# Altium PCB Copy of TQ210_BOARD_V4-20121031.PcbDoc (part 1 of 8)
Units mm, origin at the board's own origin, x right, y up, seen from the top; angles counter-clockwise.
Board outline 191.2 x 131.27 mm, 2 copper layers (TopLayer, BottomLayer); 362 components, 455 nets, 1594 pads, 630 vias.
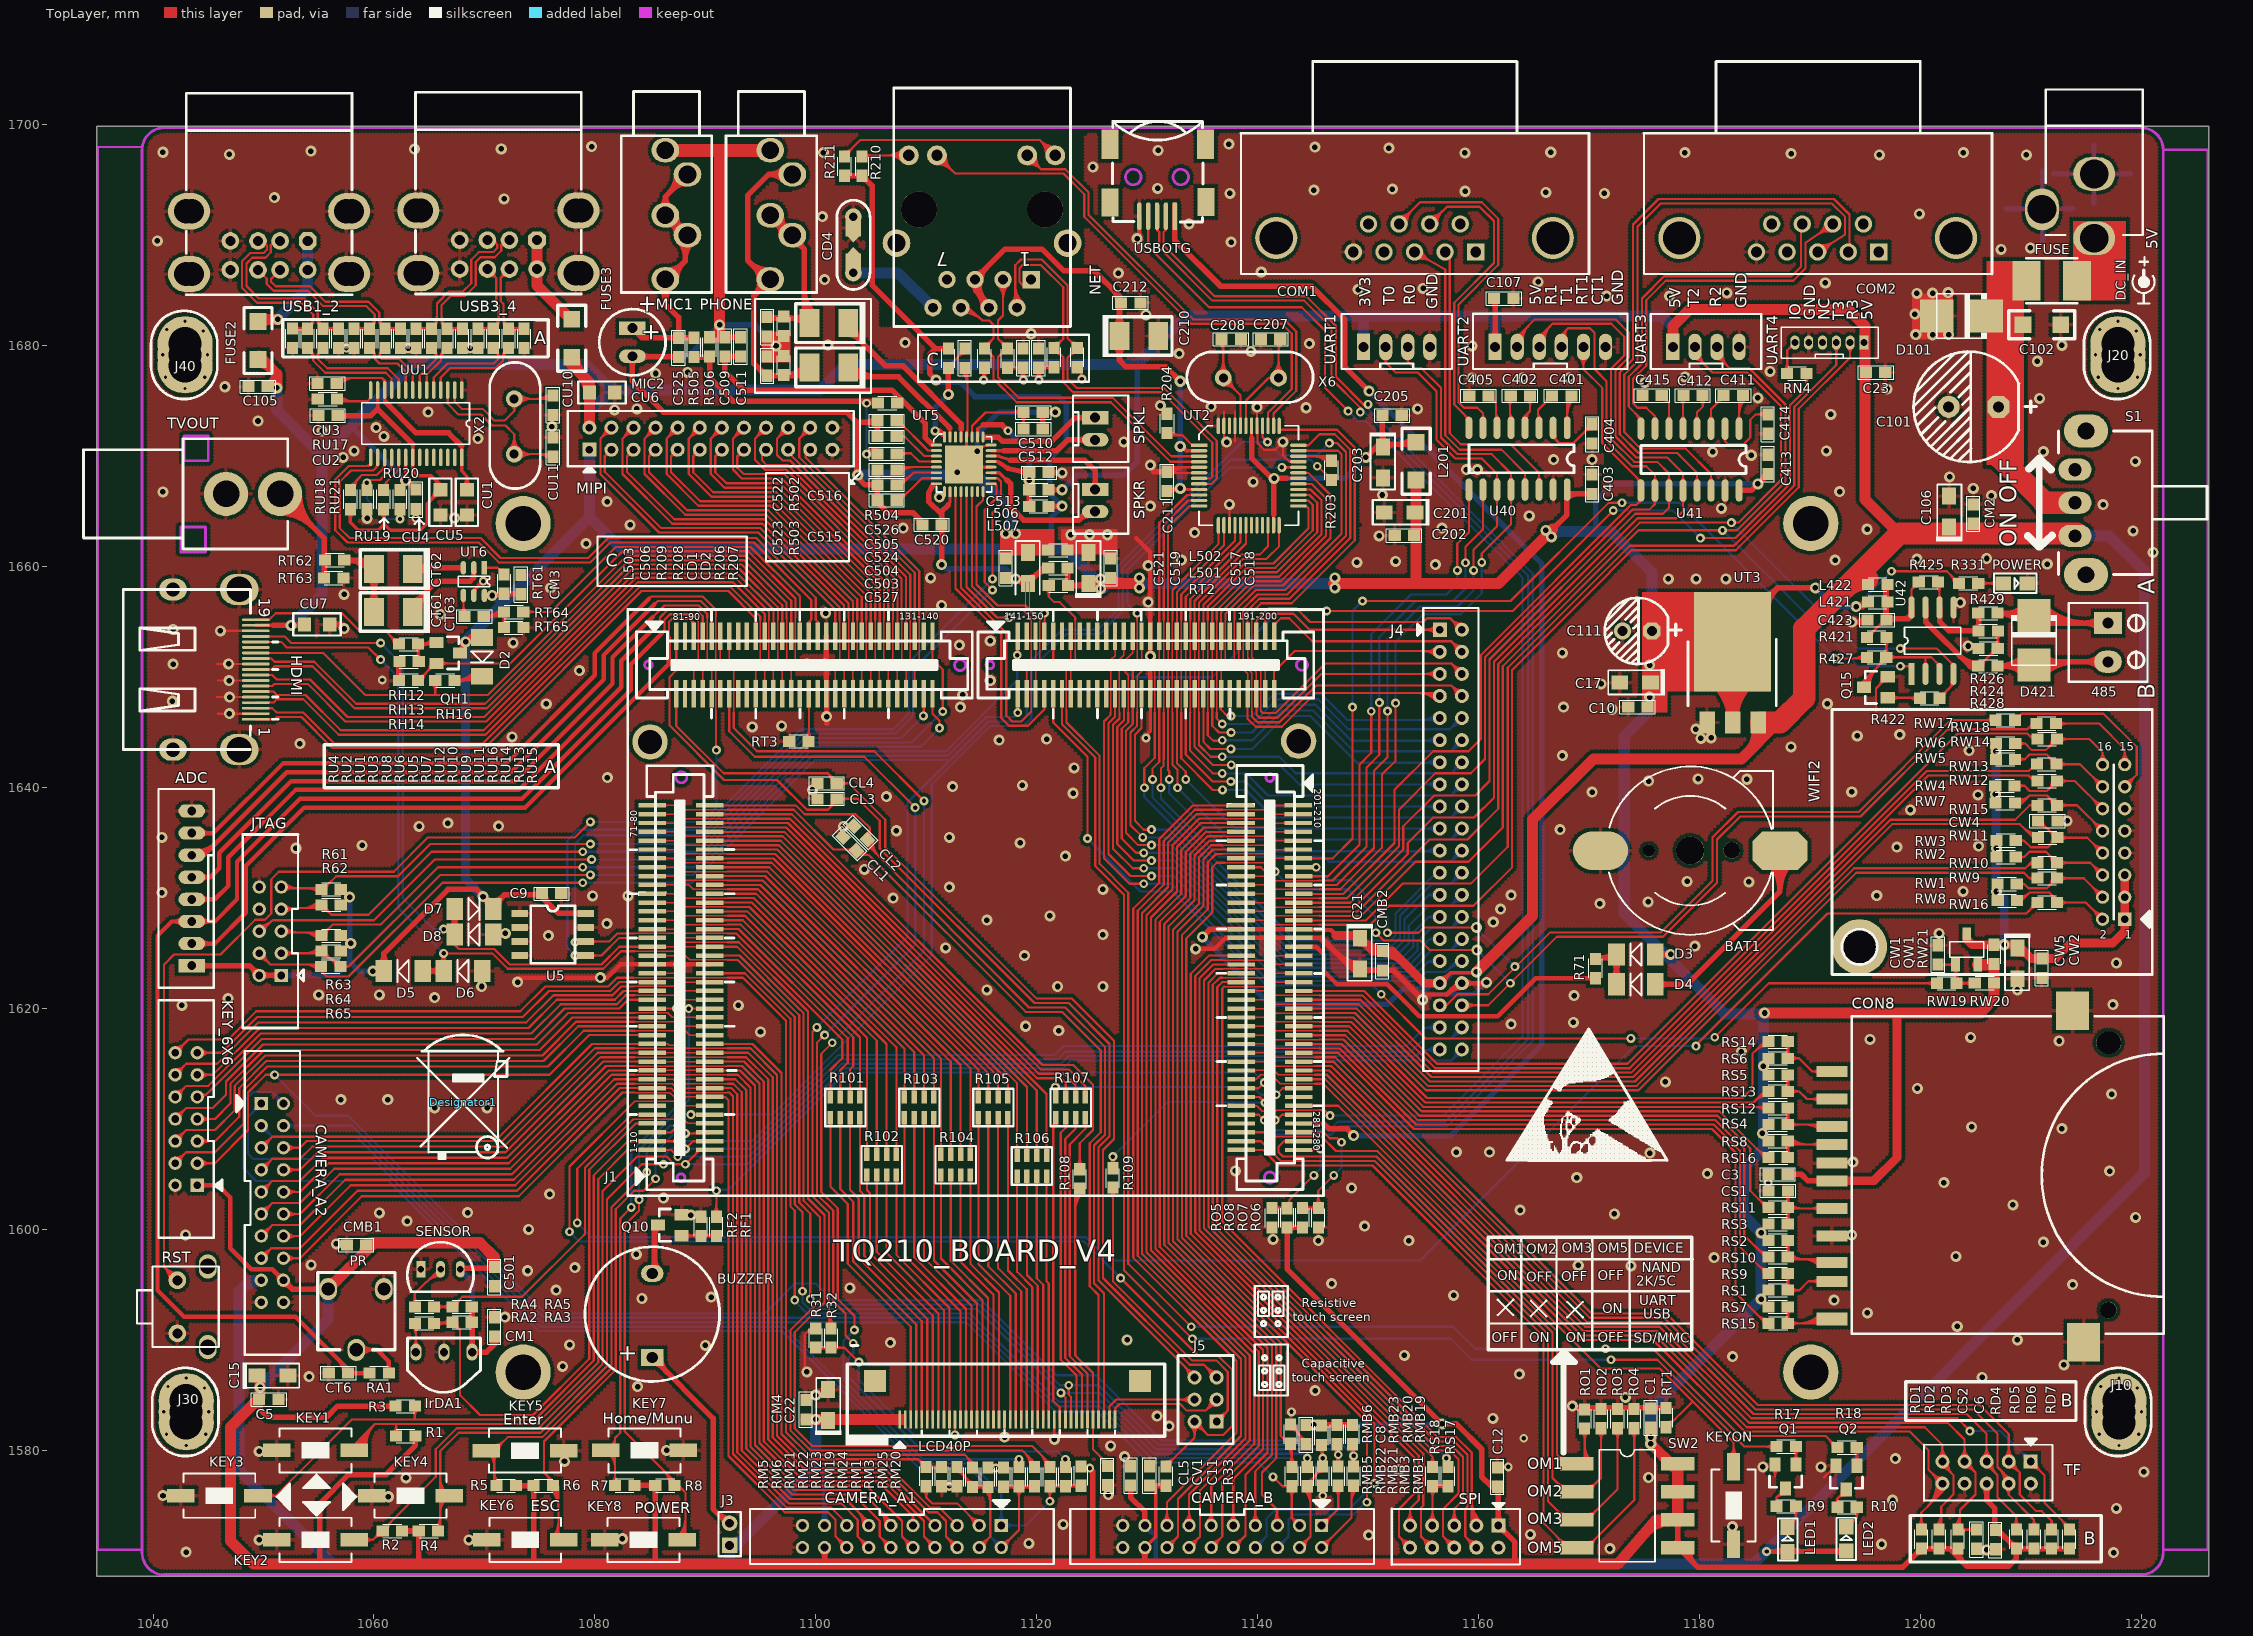
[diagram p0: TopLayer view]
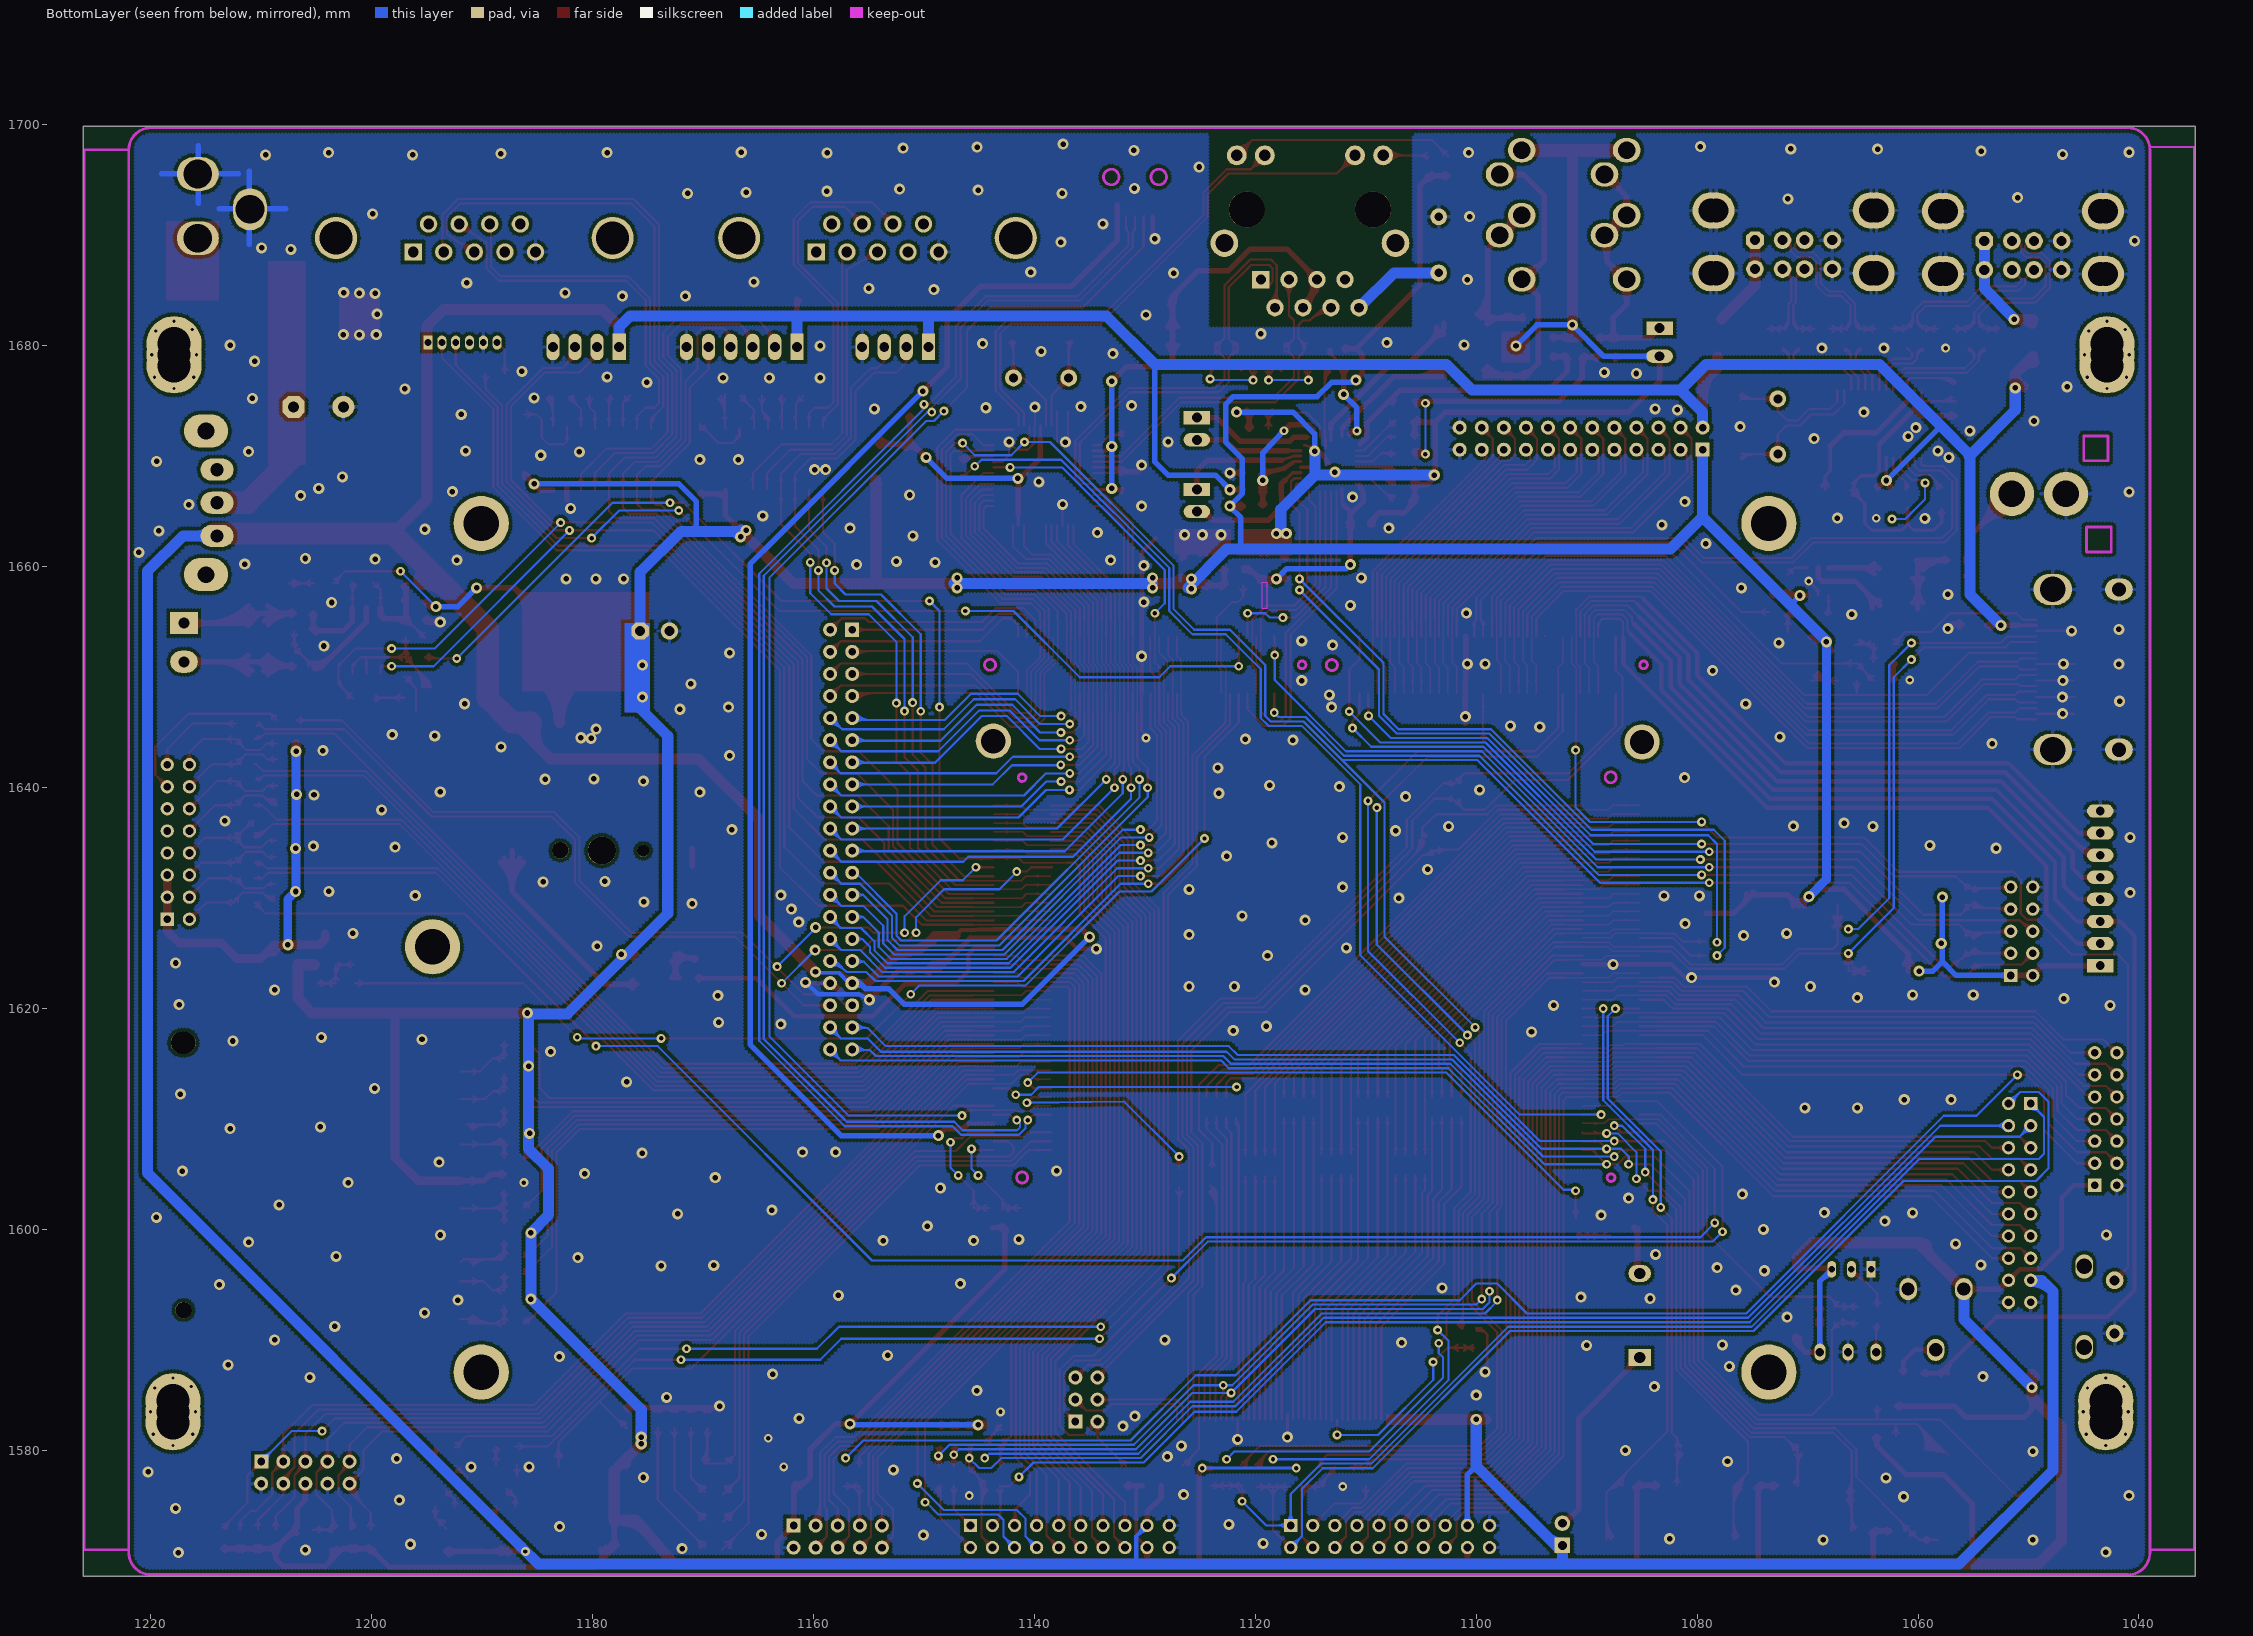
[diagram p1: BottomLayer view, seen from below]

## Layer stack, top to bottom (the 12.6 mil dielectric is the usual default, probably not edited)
TopSolder: solder mask 0.0102, Solder Resist, Dk 3.5
TopLayer: signal copper 0.0356
Dielectric1: dielectric 0.32, FR-4, Dk 4.8
BottomLayer: signal copper 0.0356
BottomSolder: solder mask 0.0102, Solder Resist, Dk 3.5

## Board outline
1034.9,1568.607 1226.1,1568.607 1226.1,1699.877 1034.9,1699.877

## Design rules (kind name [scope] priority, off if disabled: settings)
AssemblyTestPointUsage [All] p0: scope1count=1 scope1_0_kind=Board scope1_0_value=Board scope2count=1 scope2_0_kind=Board scope2_0_value=Board commentlength=0
AssemblyTestpoint [All] p0: scope1count=1 scope1_0_kind=Board scope1_0_value=Board scope2count=1 scope2_0_kind=Board scope2_0_value=Board commentlength=0
Clearance [All] p0: scope1count=1 scope1_0_kind=Board scope1_0_value=Board scope2count=1 scope2_0_kind=Board scope2_0_value=Board commentlength=0 gap=0.102
Clearance Clearance_2 [All] p0 off: scope1count=1 scope1_0_kind=Board scope1_0_value=Board scope2count=1 scope2_0_kind=Board scope2_0_value=Board commentlength=0 gap=0.2
Clearance Clearance_1 [All] p0 off: scope1count=1 scope1_0_kind=Board scope1_0_value=Board scope2count=1 scope2_0_kind=Board scope2_0_value=Board commentlength=47 gap=0.3 // Protel DXP Scope 1 Expression Was: (InPoly)
Clearance Clearance_1 [(InPoly)] p1: gap=0.3 ignorepadtopadclearanceinfootprint=FALSE
Clearance Clearance_2 [All] p2 off: gap=0.2 ignorepadtopadclearanceinfootprint=FALSE
Clearance [All] p3: gap=0.102 ignorepadtopadclearanceinfootprint=FALSE
ComponentClearance [All] p0 off: scope1count=1 scope1_0_kind=Board scope1_0_value=Board scope2count=1 scope2_0_kind=Board scope2_0_value=Board commentlength=0 gap=0.254 collisioncheckmode=3
ComponentClearance [All] p1 off: gap=0.254 collisioncheckmode=3 verticalgap=0.254 showdistances=FALSE
DiffPairsRouting [All] p0: scope1count=1 scope1_0_kind=Board scope1_0_value=Board scope2count=1 scope2_0_kind=Board scope2_0_value=Board commentlength=0
FabricationTestPointUsage TestPointUsage [All] p0: scope1count=1 scope1_0_kind=Board scope1_0_value=Board scope2count=1 scope2_0_kind=Board scope2_0_value=Board commentlength=0 valid=0 allowmultiple=FALSE
FabricationTestPointUsage TestPointUsage [All] p1: valid=0 allowmultiple=FALSE
FabricationTestpoint Testpoint [All] p0: scope1count=1 scope1_0_kind=Board scope1_0_value=Board scope2count=1 scope2_0_kind=Board scope2_0_value=Board commentlength=0 side=3 testpointundercomponent=TRUE minsize=1.016 maxsize=2.54 preferedsize=1.524 minholesize=0.508 maxholesize=1.016 preferedholesize=0.813 testpointgrid=0.025
FabricationTestpoint Testpoint [All] p1: side=3 testpointundercomponent=TRUE minsize=1.016 maxsize=2.54 preferedsize=1.524 minholesize=0.508 maxholesize=1.016 preferedholesize=0.813 testpointgrid=0.025 allowsidetop=TRUE allowsidebottom=TRUE usegrid=TRUE gridtolerance=0
FanoutControl Fanout_BGA [All] p0 off: scope1count=1 scope1_0_kind=Board scope1_0_value=Board scope2count=1 scope2_0_kind=Board scope2_0_value=Board commentlength=69 // Protel DXP Scope 1 Expression Was: IsBGA   Fanout_BGA (Default Rule)
FanoutControl Fanout_LCC [All] p0 off: scope1count=1 scope1_0_kind=Board scope1_0_value=Board scope2count=1 scope2_0_kind=Board scope2_0_value=Board commentlength=69 // Protel DXP Scope 1 Expression Was: IsLCC   Fanout_LCC (Default Rule)
FanoutControl Fanout_SOIC [All] p0 off: scope1count=1 scope1_0_kind=Board scope1_0_value=Board scope2count=1 scope2_0_kind=Board scope2_0_value=Board commentlength=71 // Protel DXP Scope 1 Expression Was: IsSOIC   Fanout_SOIC (Default Rule)
FanoutControl Fanout_Small [All] p0 off: scope1count=1 scope1_0_kind=Board scope1_0_value=Board scope2count=1 scope2_0_kind=Board scope2_0_value=Board commentlength=84 // Protel DXP Scope 1 Expression Was: (CompPinCount < 5)   Fanout_Small (Default Rule)
FanoutControl Fanout_Default [All] p0: scope1count=1 scope1_0_kind=Board scope1_0_value=Board scope2count=1 scope2_0_kind=Board scope2_0_value=Board commentlength=30 // Fanout_Default (Default Rule)
Height [All] p0: scope1count=1 scope1_0_kind=Board scope1_0_value=Board scope2count=1 scope2_0_kind=Board scope2_0_value=Board commentlength=0
HoleSize [All] p0: scope1count=1 scope1_0_kind=Board scope1_0_value=Board scope2count=1 scope2_0_kind=Board scope2_0_value=Board commentlength=0 absolutevalues=TRUE maxlimit=8 minlimit=0.025 maxpercent=80.000 minpercent=20.000
HoleSize [All] p1: absolutevalues=TRUE maxlimit=8 minlimit=0.025 maxpercent=80.000 minpercent=20.000
HoleToHoleClearance [All] p0: scope1count=1 scope1_0_kind=Board scope1_0_value=Board scope2count=1 scope2_0_kind=Board scope2_0_value=Board commentlength=0
LayerPairs [All] p0: scope1count=1 scope1_0_kind=Board scope1_0_value=Board scope2count=1 scope2_0_kind=Board scope2_0_value=Board commentlength=0 enforce=TRUE
MinimumSolderMaskSliver [All] p0: scope1count=1 scope1_0_kind=Board scope1_0_value=Board scope2count=1 scope2_0_kind=Board scope2_0_value=Board commentlength=0
NetAntennae [All] p0: scope1count=1 scope1_0_kind=Board scope1_0_value=Board scope2count=1 scope2_0_kind=Board scope2_0_value=Board commentlength=0
PasteMaskExpansion [All] p0: scope1count=1 scope1_0_kind=Board scope1_0_value=Board scope2count=1 scope2_0_kind=Board scope2_0_value=Board commentlength=0 expansion=0
PlaneClearance [All] p0: scope1count=1 scope1_0_kind=Board scope1_0_value=Board scope2count=1 scope2_0_kind=Board scope2_0_value=Board commentlength=0 clearance=0.508
PlaneConnect [All] p0: scope1count=1 scope1_0_kind=Board scope1_0_value=Board scope2count=1 scope2_0_kind=Board scope2_0_value=Board commentlength=0 planeconnectstyle=Relief reliefexpansion=0.508 reliefentries=4 reliefconductorwidth=0.254 reliefairgap=0.254
PolygonConnect [All] p0: scope1count=1 scope1_0_kind=Board scope1_0_value=Board scope2count=1 scope2_0_kind=Board scope2_0_value=Board commentlength=0 connectstyle=Relief reliefconductorwidth=0.3 reliefentries=4 polygonreliefangle="90 Angle"
PolygonConnect [All] p1: connectstyle=Relief reliefconductorwidth=0.3 reliefentries=4 polygonreliefangle="90 Angle" airgapwidth=0.254
RoutingCorners [All] p0: scope1count=1 scope1_0_kind=Board scope1_0_value=Board scope2count=1 scope2_0_kind=Board scope2_0_value=Board commentlength=0 cornerstyle=45-Degree minsetback=2.54 maxsetback=2.54
RoutingLayers [All] p0: scope1count=1 scope1_0_kind=Board scope1_0_value=Board scope2count=1 scope2_0_kind=Board scope2_0_value=Board commentlength=0 top layer=Horizontal bottom layer=Vertical
RoutingPriority [All] p0: scope1count=1 scope1_0_kind=Board scope1_0_value=Board scope2count=1 scope2_0_kind=Board scope2_0_value=Board commentlength=0
RoutingTopology [All] p0: scope1count=1 scope1_0_kind=Board scope1_0_value=Board scope2count=1 scope2_0_kind=Board scope2_0_value=Board commentlength=0 topology=Shortest
RoutingVias [All] p0: scope1count=1 scope1_0_kind=Board scope1_0_value=Board scope2count=1 scope2_0_kind=Board scope2_0_value=Board commentlength=0 holewidth=0.711 width=1.27 viastyle="Through Hole" minholewidth=0.711 minwidth=1.27 maxholewidth=5 maxwidth=5
RoutingVias [All] p1: holewidth=0.711 width=1.27 viastyle="Through Hole" minholewidth=0.711 minwidth=1.27 maxholewidth=5 maxwidth=5
ShortCircuit [All] p0: scope1count=1 scope1_0_kind=Board scope1_0_value=Board scope2count=1 scope2_0_kind=Board scope2_0_value=Board commentlength=0 allowed=FALSE
SilkToBoardRegionClearance [All] p0: scope1count=1 scope1_0_kind=Board scope1_0_value=Board scope2count=1 scope2_0_kind=Board scope2_0_value=Board commentlength=0
SilkToSilkClearance [All] p0: scope1count=1 scope1_0_kind=Board scope1_0_value=Board scope2count=1 scope2_0_kind=Board scope2_0_value=Board commentlength=0
SilkToSolderMaskClearance [All] p0 off: scope1count=1 scope1_0_kind=Board scope1_0_value=Board scope2count=1 scope2_0_kind=Board scope2_0_value=Board commentlength=44 // Protel DXP Scope 1 Expression Was: IsPad
SolderMaskExpansion [All] p0: scope1count=1 scope1_0_kind=Board scope1_0_value=Board scope2count=1 scope2_0_kind=Board scope2_0_value=Board commentlength=0 expansion=0.102
SolderMaskExpansion [All] p1: expansion=0.102
UnRoutedNet [All] p0: scope1count=1 scope1_0_kind=Board scope1_0_value=Board scope2count=1 scope2_0_kind=Board scope2_0_value=Board commentlength=0
UnpouredPolygon [All] p0: scope1count=1 scope1_0_kind=Board scope1_0_value=Board scope2count=1 scope2_0_kind=Board scope2_0_value=Board commentlength=0
Width Width_7 [All] p0 off: scope1count=1 scope1_0_kind=Net scope1_0_value=VDD5V scope2count=1 scope2_0_kind=Board scope2_0_value=Board commentlength=0 maxlimit=0.5 minlimit=0.5 preferedwidth=0.5
Width Width_2 [All] p0 off: scope1count=1 scope1_0_kind=Net scope1_0_value=XMMC1DATA3 scope2count=1 scope2_0_kind=Board scope2_0_value=Board commentlength=0 maxlimit=0.5 minlimit=0.5 preferedwidth=0.5
Width [All] p0 off: scope1count=1 scope1_0_kind=Board scope1_0_value=Board scope2count=1 scope2_0_kind=Board scope2_0_value=Board commentlength=0 maxlimit=0.152 minlimit=0.127 preferedwidth=0.135
Width Width_1 [All] p0: scope1count=1 scope1_0_kind=Board scope1_0_value=Board scope2count=1 scope2_0_kind=Board scope2_0_value=Board commentlength=0 maxlimit=3 minlimit=0.2 preferedwidth=0.5
Width Width_2 [InNet('XMMC1DATA3')] p1 off: maxlimit=0.5 minlimit=0.5 preferedwidth=0.5
Width Width_7 [InNet('VDD5V')] p2 off: maxlimit=0.5 minlimit=0.5 preferedwidth=0.5
Width [All] p3 off: maxlimit=0.152 minlimit=0.127 preferedwidth=0.135
Width Width_1 [All] p4: maxlimit=3 minlimit=0.2 preferedwidth=0.5
26 further rules are at their usual default settings.

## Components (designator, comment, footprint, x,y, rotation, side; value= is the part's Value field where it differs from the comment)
485 "CON2_3.5" CN2-3.5-180 1217,1654.9 r90 top
ADC "CON8" DIP8_2.0 1043.5,1623.9 r90 top
BAT1 "BATTERY" BAT600 1187.3,1634.3 r90 top
BUZZER "BUZZER" BUZZER 1085.2,1588.4 r90 top
C1 "104" C_0603#1 1175.6,1582.05 r90 top
C3 "104" C_0603#1 1188,1605 r180 top
C5 "104" C_0603#1 1049.6,1584.6 r0 top
C6 "104" C_0603#1 1206.8,1572.8 r270 top
C8 "104" C_0603#2 1144.4,1582.3 r270 top
C9 "104" C_0603#1 1075.2,1630.4 r0 top
C10 "104" C_0603#2 1175.3,1647.3 r180 top
C11 "104" C_0603#3 1130.2,1576.8 r90 top
C12 "104" C_0603#3 1161.7,1576.7 r90 top
C15 "22uF/6.3V" 3216A#1 1049.4,1586.8 r0 top
C17 "10uF/16V" 3216A#1 1175.6,1649.5 r180 top
C21 "10uF/16V" 3216A#1 1149.278,1626.384 r270 top
C22 "10uF/16V" 3216A#2 1101.1,1582.7 r90 top
C23 "104" C_0603#4 1195.1,1677.6 r0 top
C101 "220uF/50V" 1000UF 1202.6,1674.5 r0 top
C102 "10uF/25V" 1206#1 1209.3,1681.9 r0 top
C105 "104" C_0603#3 1050.4,1676.3 r180 top
C106 "10uF/16V" 3216a 1202.6,1663.6 r90 top
C107 "104" C_0603#3 1161.4,1684.3 r0 top
C111 "220uF/16V" 47U1 1175.7,1654.2 r180 top
C201 "22uF/6.3V" 3216A#3 1154.266,1664.923 r180 top
C202 "104" C_0603#1 1154.166,1662.823 r180 top
C203 "22uF/6.3V" 3216A#3 1151.354,1670.848 r270 top
C205 "104" C_0603#1 1151.3,1673.7 r0 top
C207 "22pF" C_0603#1 1140.3,1680.6 r0 top
C208 "22pF" C_0603#1 1138.5,1680.6 r180 top
C210 "100uF/6.3V" C_1210#1 1127.5,1680.9 r0 top
C211 "22pF" C_0603#1 1131.8,1668.6 r270 top
C212 "104" C_0603#1 1129.4,1683.9 r180 top
C401 "104" C_0603#1 1166.669,1675.48 r0 top
C402 "104" C_0603#1 1164.669,1675.48 r180 top
C403 "104" C_0603#1 1170.3,1666.6 r90 top
C404 "104" C_0603#1 1170.3,1672.9 r270 top
C405 "104" C_0603#1 1160.919,1675.48 r180 top
C411 "104" C_0603#1 1182.2,1675.5 r0 top
C412 "104" C_0603#1 1180.3,1675.5 r180 top
C413 "104" C_0603#1 1186.2,1668.4 r90 top
C414 "104" C_0603#1 1186.2,1673.8 r270 top
C415 "104" C_0603#1 1176.6,1675.5 r180 top
C423 "104" C_0603#5 1195.2,1655.2 r0 top
C501 "104" C_0603#2 1070.9,1596.6 r270 top
C503 "1uF" C_0603#1 1107.328,1667.424 r180 top
C504 "1uF" C_0603#1 1107.329,1668.778 r180 top
C505 "1uF" C_0603#1 1107.329,1671.778 r180 top
C506 "104" C_0603#1 1113.5,1678 r90 top
C509 "1uF" C_0603#1 1091.781,1679.033 r90 top
C510 "1uF" C_0603#1 1118.808,1673.973 r0 top
C511 "104" C_0603#1 1093.181,1679.033 r90 top
C512 "104" C_0603#1 1118.808,1672.473 r0 top
C513 "104" C_0603#1 1119.328,1668.524 r0 top
C515 "100uF/6.3V" C_1210#1 1102.939,1678.054 r180 top
C516 "100uF/6.3V" C_1210#1 1102.939,1682.054 r180 top
C517 "22uF/6.3V" 3216A#3 1124.7,1658.5 r90 top
C518 "104" C_0603#1 1126.7,1659 r90 top
C519 "22uF/6.3V" 3216A#4 1119.2,1658.5 r90 top
C520 "104" C_0603#1 1111.4,1663.8 r180 top
C521 "104" C_0603#1 1117.2,1659 r90 top
C522 "220pF" C_0603#1 1095.6,1682.6 r270 top
C523 "220pF" C_0603#1 1095.6,1677.3 r90 top
C524 "1uF" C_0603#1 1107.328,1670.224 r180 top
C525 "220pF" C_0603#1 1087.574,1680.736 r270 top
C526 "1uF" C_0603#1 1107.328,1673.224 r180 top
C527 "1uF" C_0603#1 1107.328,1666.024 r180 top
CAMERA_A1 "CAM_2.0" IDC20S_2.0 1116.8,1573.2 r180 top
CAMERA_A2 "CAM_2.0" IDC20S_2.0 1049.8,1611.4 r270 top
CAMERA_B "CAM_2.0" IDC20S_2.0 1145.8,1573.2 r180 top
CD1 "104" C_0603#1 1118.777,1678.015 r90 top
CD2 "104" C_0603#1 1120.177,1678.015 r90 top
CD4 "102/1kv" RESD1 1103.4,1686.6 r90 top
CL1 "1nF(NC)" C_0603#6 1103.7,1634.3 r135 top
CL2 "1nF(NC)" C_0603#6 1104.7,1635.3 r135 top
CL3 "1nF(NC)" C_0603#6 1101.9,1639 r180 top
CL4 "1nF(NC)" C_0603#6 1101.9,1640.4 r180 top
CL5 "22pF" C_0603#1 1126.4,1578.6 r270 top
CM1 "104" C_0603#1 1070.9,1590.3 r90 top
CM2 "104" C_0603#1 1204.8,1663.9 r90 top
CM3 "104" C_0603#7 1073.3,1657.5 r90 top
CM4 "104" C_0603#7 1099.1,1582.8 r90 top
CMB1 "104" C_0603#1 1059.3,1598.6 r180 top
CMB2 "104" C_0603#1 1151.3,1625.2 r270 top
COM1 "BOXCONN_DB9" DB9RA/M 1159.75,1688.5 r180 top
COM2 "BOXCONN_DB9" DB9RA/M 1196.25,1688.5 r180 top
CON8 "SD/MMC CARD" SD-5011 1191.995,1611.805 r0 top locked
CS1 "22pF" C_0603#8 1188,1603.5 r180 top
CS2 "22pF" C_0603#8 1205.1,1572.819 r270 top
CT6 "104" C_0603#1 1055.9,1587 r0 top
CT61 "47uF/10V" C_1210#2 1063.5,1655.9 r180 top
CT62 "47uF/10V" C_1210#2 1063.5,1659.8 r180 top
CT63 "104" C_0603#9 1068.2,1655.5 r0 top
CU1 "10uF" 0805C#1 1068.4,1667 r0 top
CU2 "104" C_0603#8 1056.7,1673.7 r180 top
CU3 "104" C_0603#8 1054.9,1676.6 r0 top
CU4 "104" C_0603#1 1063.798,1666.997 r270 top
CU5 "10uF" 0805C#2 1066,1667 r0 top
CU6 "10uF" 0805C#3 1079.5,1675.8 r270 top
CU7 "10uF" 0805C#4 1053.7,1654.8 r270 top
CU10 "22pF" C_0603#8 1076.202,1673.769 r90 top
CU11 "22pF" C_0603#8 1076.2,1671.7 r270 top
CV1 "104" C_0603#3 1128.5,1576.8 r90 top
CW1 "1nF(NC)" C_0603#10 1201.6,1624 r90 top
CW2 "104" C_0603#10 1211,1622.8 r90 top
CW4 "22pF" C_0603#11 1212.4,1637 r180 top
CW5 "22uF/6.3V" 3216A#5 1208.8,1625.5 r270 top
D2 "1N4148" D1206 1069.8,1653.6 r270 top
D3 "1N4148" D1206 1176,1624.9 r180 top
D4 "1N4148" D1206 1176,1622.2 r180 top
D5 "1N4148" D1206 1064.4,1623.4 r180 top
D6 "1N4148" D1206 1069.8,1623.4 r180 top
D7 "1N4148" D1206 1067.3,1629 r0 top
D8 "1N4148" D1206 1070.8,1626.7 r180 top
D101 "SMBJ6.8A" SMBJ_SMD 1201.5,1682.7 r180 top
D421 "SMBJ6.8A" SMBJ_SMD 1210.3,1651.1 r270 top
DC_IN "DC-05-2.1" DC-JACK 1215.75,1689.75 r90 top
Designator1 "Comment" LAJITONG 1068.1,1611.5 r0 top
FUSE "2.6A" FUSE 1214.2,1685.9 r180 top
FUSE2 "2A" 1206#2 1049.5,1682.2 r270 top
FUSE3 "2A" 1206#1 1077.9,1682.4 r270 top
HDMI "HDMI_A" HDMI 1049.3,1646.2 r0 top
IrDA1 "HS0038B" IRM3638 1063.8,1588.9 r0 top
J1 "CON280" CON280_SMD_BOT 1085.2,1607.2 r0 top locked
J3 "CON2" SIP2_2.0 1092.2,1571.4 r90 top
J4 "HEADER 20X2" IDC40P_2.00 1156.5,1654.3 r270 top
J5 "CON6_DIP" CON6_2.0 1136.3,1582.6 r90 top
J10 "TP" DWK 1217.998,1583.497 r0 top locked
J20 "TP" DWK 1217.898,1679.197 r0 top locked
J30 "TP" DWK 1042.998,1583.497 r0 top locked
J40 "TP" DWK 1042.898,1679.197 r0 top locked
JTAG "HEADER 5X2" IDC10S 1051.6,1623 r90 top
KEY1 "KEY" SW-PB2 1058.2,1580 r270 top
KEY2 "KEY" SW-PB2 1058.2,1571.9 r270 top
KEY3 "KEY" SW-PB2 1049.5,1575.9 r270 top
KEY4 "KEY" SW-PB2 1066.8,1575.9 r270 top
KEY5 "KEY" SW-PB2 1070.176,1579.976 r90 top
KEY6 "KEY" SW-PB2 1077.2,1571.9 r270 top
KEY7 "KEY" SW-PB2 1081,1580 r90 top
KEY8 "KEY" SW-PB2 1087.9,1571.9 r270 top
KEY_6X6 "HEADER 7X2" IDC14S_2.0 1044,1604 r90 top
KEYON "KEY" SW-PB2 1183.098,1578.502 r0 top
L201 "10uH" 1206#2 1154.354,1667.848 r90 top
L421 "0R" R_0603#1 1195.3,1656.8 r0 top
L422 "0(NC)" R_0603#1 1195.3,1658.4 r0 top
L501 "0" R_0603#2 1122.8,1659.9 r180 top
L502 "0" R_0603#2 1122.8,1661.5 r180 top
L503 "F.B/120" R_0603#2 1112,1678 r90 top
L506 "0" R_0603#2 1119.328,1666.976 r0 top
L507 "0(NC)" R_0603#2 1119.328,1665.476 r0 top
LCD40P "LCD40P" FPC0.5-SMT-40P 1107.6,1582.8 r0 top
LED1 "" LED_0805#1 1187.991,1573.041 r270 top
LED2 "" LED_0805#1 1193.3,1573.1 r270 top
MIC1 "PJ-215-B" PJ-215-B 1086.385,1697.725 r270 top
MIC2 "MIC" MIC 1083.4,1681.6 r270 top
MIPI "CON24(NC)" IDC24P_2.0 1079.5,1670.6 r0 top locked
NET "HR911105A" HR911105A 1119.5,1686 r90 top
PHONE "PJ-215-B" PJ-215-B 1095.885,1697.725 r270 top
POWER "RED" LED_0805#2 1209.7,1658.5 r180 top
PR "3K" RP2 1060.9,1594.6 r270 top
Q1 "S8050" S9013SMD#1 1187.791,1576.541 r180 top
Q2 "S8050" S9013SMD#1 1193.3,1576.45 r180 top
Q10 "S8050" S9013SMD#1 1085.7,1600.4 r90 top
Q15 "S8050" S9013SMD#1 1194.9,1649.1 r90 top
QH1 "S8050" S9013SMD#2 1067.8,1652.2 r270 top
QW1 "AP2305GN(NC)" SOT23-3 1203.2,1624 r0 top
R1 "10K" R_0603#2 1062,1581.3 r0 top
R2 "10K" R_0603#2 1060.8,1572.7 r0 top
R3 "10K" R_0603#3 1063.692,1584.011 r180 top
R4 "10K" R_0603#2 1065.8,1572.7 r180 top
R5 "10K" R_0603#2 1071.1,1576.8 r0 top
R6 "10K" R_0603#2 1076.2,1576.8 r180 top
R7 "10K" R_0603#2 1081.824,1576.824 r0 top
R8 "10K" R_0603#2 1087.224,1576.824 r180 top
R9 "1K" R_0603#2 1186.991,1574.941 r0 top
R10 "1K" R_0603#2 1192.5,1574.85 r0 top
R17 "10K" R_0603#2 1186.991,1580.341 r0 top
R18 "10K" R_0603#2 1192.5,1580.25 r0 top
R31 "0" R_0603#2 1100,1589.3 r90 top
R32 "0(NC)" R_0603#2 1101.4,1589.3 r90 top
R33 "0(NC)" R_0603#2 1131.7,1576.8 r90 top
R61 "10K" R_0603#4 1057,1630.8 r180 top
R62 "10K" R_0603#4 1057,1629.4 r180 top
R63 "10K" R_0603#4 1057,1626.6 r180 top
R64 "10K" R_0603#4 1057,1625.2 r180 top
R65 "1K" R_0603#4 1055.2,1623.8 r0 top
R71 "10K" R_0603#2 1170.6,1624.5 r270 top
R101 "22R" 8P4R_0603 1104,1612 r270 top
R102 "22R" 8P4R_0603 1107.3,1606.8 r270 top
R103 "22R" 8P4R_0603 1110.7,1612 r270 top
R104 "22R" 8P4R_0603 1114,1606.8 r270 top
R105 "22R" 8P4R_0603 1117.4,1612 r270 top
R106 "22R" 8P4R_0603 1120.9,1606.7 r270 top
R107 "22R" 8P4R_0603 1124.411,1612 r270 top
R108 "22" R_0603#2 1123.9,1603.7 r90 top
R109 "22" R_0603#2 1126.9,1603.8 r90 top
R203 "0" R_0603#2 1146.7,1669.6 r270 top
R204 "6.8K(1%)" R_0603#2 1131.8,1672.1 r90 top
R206 "51" R_0603#2 1121.577,1679.815 r270 top
R207 "51" R_0603#2 1123.677,1679.815 r270 top
R208 "51" R_0603#2 1117.377,1678.015 r90 top
R209 "51" R_0603#2 1115.277,1678.015 r90 top
R210 "1K" R_0603#2 1102.6,1695.4 r90 top
R211 "1K" R_0603#2 1104.2,1695.4 r90 top
R331 "1K" R_0603#5 1203.5,1658.5 r0 top
R421 "5.1K" R_0603#1 1195.2,1653.6 r0 top
R422 "1K" R_0603#1 1200,1648.1 r0 top
R424 "2K" R_0603#1 1207,1652.6 r180 top
R425 "2K" R_0603#1 1201.6,1658.6 r180 top
R426 "120" R_0603#1 1205.3,1654.2 r0 top
R427 "0(NC)" R_0603#1 1196.9,1651.8 r180 top
R428 "22" R_0603#2 1207,1651 r180 top
R429 "22" R_0603#2 1207,1655.8 r180 top
R502 "47K" R_0603#2 1097.1,1680.9 r90 top
R503 "47K" R_0603#2 1097.1,1679.1 r270 top
R504 "2.2K" R_0603#2 1105.628,1674.824 r0 top
R505 "0" R_0603#2 1088.981,1680.733 r270 top
R506 "47K(NC)" R_0603#2 1090.381,1679.033 r90 top
RA1 "100" R_0603#2 1059.6,1587 r0 top
RA2 "0" R_0603#2 1063.7,1591.5 r0 top
RA3 "10K" R_0603#2 1067.1,1591.6 r0 top
RA4 "0" R_0603#2 1063.7,1593 r0 top
RA5 "10K" R_0603#2 1067.1,1593 r0 top
RD1 "10K" R_0603#2 1200.1,1571.1 r90 top
RD2 "10K" R_0603#2 1201.7,1571.1 r90 top
RD3 "10K" R_0603#2 1203.4,1571.1 r90 top
RD4 "10K" R_0603#2 1208.7,1571.1 r90 top
RD5 "10K" R_0603#2 1210.3,1571.1 r90 top
RD6 "10K" R_0603#2 1211.9,1571.1 r90 top
RD7 "10K" R_0603#2 1213.5,1571.1 r90 top
RF1 "100" R_0603#5 1091,1599.4 r90 top
RF2 "5.1K" R_0603#5 1089.6,1599.4 r90 top
RH12 "10K" R_0603#5 1064,1653 r180 top
RH13 "10K" R_0603#5 1062.3,1651.4 r0 top
RH14 "100K" R_0603#5 1064,1649.7 r180 top
RH16 "1.5K" R_0603#2 1067.3,1649.7 r180 top
RM1 "0(NC)" R_0603#2 1119.8,1576.748 r90 top
RM3 "0(NC)" R_0603#2 1121.2,1576.748 r90 top
RM5 "0" R_0603#2 1110,1578.5 r270 top
RM6 "10K" R_0603#2 1111.4,1578.5 r270 top
RM19 "4.7K" R_0603#5 1117,1578.448 r270 top
RM20 "4.7K" R_0603#5 1124,1578.548 r270 top
RM21 "10K" R_0603#5 1112.8,1576.752 r90 top
RM22 "0" R_0603#2 1114.2,1578.448 r270 top
RM23 "10K(NC)" R_0603#2 1115.6,1578.448 r270 top
RM24 "0" R_0603#2 1118.4,1576.748 r90 top
RM25 "0" R_0603#2 1122.6,1576.748 r90 top
RMB1 "0" R_0603#2 1148.7,1576.8 r90 top
RMB3 "0" R_0603#2 1147.3,1576.8 r90 top
RMB5 "0" R_0603#2 1143.1,1578.5 r270 top
RMB6 "10K" R_0603#2 1143,1580.6 r90 top
RMB19 "4.7K(NC)" R_0603#2 1148.6,1582.3 r270 top
RMB20 "4.7K(NC)" R_0603#2 1147.2,1582.3 r270 top
RMB21 "10K" R_0603#2 1145.9,1576.8 r90 top
RMB22 "0" R_0603#2 1144.5,1578.5 r270 top
RMB23 "10K(NC)" R_0603#2 1145.8,1580.5 r90 top
RN4 "0" R_0603#2 1189.7,1677.5 r180 top
RO1 "10K" R_0603#3 1169.611,1583.708 r270 top
RO2 "10K" R_0603#3 1171.111,1582.008 r90 top
RO3 "10K" R_0603#3 1172.611,1582.008 r90 top
RO4 "10K" R_0603#3 1174.111,1582.008 r90 top
RO5 "10K" R_0603#6 1141.3,1600.172 r90 top
RO6 "10K" R_0603#6 1145.5,1600.172 r90 top
RO7 "10K(NC)" R_0603#7 1144.1,1601.922 r270 top
RO8 "10K(NC)" R_0603#7 1142.7,1601.9 r270 top
RS1 "10K" R_0603#2 1186.25,1594.5 r0 top
RS2 "10K" R_0603#2 1186.25,1599 r0 top
RS3 "10K" R_0603#2 1186.25,1600.5 r0 top
RS4 "10K" R_0603#2 1186.25,1609.5 r0 top
RS5 "10K" R_0603#2 1186.25,1614 r0 top
RS6 "10K" R_0603#2 1186.25,1615.5 r0 top
RS7 "10K" R_0603#2 1186.25,1593 r0 top
RS8 "10K" R_0603#2 1186.25,1608 r0 top
RS9 "22" R_0603#2 1186.25,1596 r0 top
RS10 "22" R_0603#2 1186.25,1597.5 r0 top
RS11 "22" R_0603#2 1186.25,1602 r0 top
RS12 "22" R_0603#2 1186.25,1611 r0 top
RS13 "22" R_0603#2 1186.25,1612.5 r0 top
RS14 "22" R_0603#2 1186.25,1617 r0 top
RS15 "22" R_0603#2 1188,1591.5 r180 top
RS16 "22" R_0603#2 1188,1606.5 r180 top
RS17 "0" R_0603#2 1157.25,1578.5 r270 top
RS18 "0(NC)" R_0603#2 1155.85,1578.5 r270 top
RST "KEY" RST_KEY 1042.2,1590.6 r90 top
RT1 "0(NC)" R_0603#2 1177,1582.1 r90 top
RT2 "0(NC)" R_0603#2 1121.1,1658.3 r0 top
RT3 "10K" R_0603#2 1097.6,1644.2 r0 top
RT61 "4.7K" R_0603#8 1071.8,1659.3 r270 top
RT62 "75" R_0603#8 1057.3,1660.6 r180 top
RT63 "75" R_0603#8 1055.5,1659 r0 top
RT64 "0" R_0603#8 1073.5,1655.9 r180 top
RT65 "75" R_0603#8 1071.79,1654.5 r0 top
RU1 "22" R_0603#2 1055.4,1679.8 r90 top
RU2 "22" R_0603#2 1054,1679.8 r90 top
RU3 "15K" R_0603#2 1056.8,1679.8 r90 top
RU4 "15K" R_0603#2 1052.62,1679.815 r90 top
RU5 "22" R_0603#2 1061,1679.8 r90 top
RU6 "22" R_0603#2 1059.6,1679.8 r90 top
RU7 "15K" R_0603#2 1062.4,1679.8 r90 top
RU8 "15K" R_0603#2 1058.2,1679.8 r90 top
RU9 "22" R_0603#2 1066.6,1679.8 r90 top
RU10 "22" R_0603#2 1065.2,1679.8 r90 top
RU11 "15K" R_0603#2 1068,1679.8 r90 top
RU12 "15K" R_0603#2 1063.8,1679.8 r90 top
RU13 "22" R_0603#2 1072.2,1679.8 r90 top
RU14 "22" R_0603#2 1070.8,1679.8 r90 top
RU15 "15K" R_0603#2 1073.6,1679.8 r90 top
RU16 "15K" R_0603#2 1069.4,1679.8 r90 top
RU17 "2.7K (1%)" R_0603#7 1056.632,1675.159 r180 top
RU18 "100K" R_0603#2 1057.865,1666.958 r270 top
RU19 "100K" R_0603#2 1060.865,1666.958 r270 top
RU20 "47K" R_0603#2 1062.365,1666.958 r270 top
RU21 "100K" R_0603#2 1059.365,1666.958 r270 top
RW1 "10K" R_0603#2 1206.993,1631.269 r0 top
RW2 "10K" R_0603#2 1206.893,1633.719 r0 top
RW3 "10K" R_0603#2 1206.893,1635.219 r0 top
RW4 "10K" R_0603#2 1206.793,1640.169 r0 top
RW5 "10K" R_0603#2 1206.843,1642.569 r0 top
RW6 "10K" R_0603#2 1206.85,1644 r0 top
RW7 "10K" R_0603#9 1206.8,1638.6 r0 top
RW8 "10K" R_0603#9 1206.993,1629.769 r0 top
RW9 "22" R_0603#9 1210.6,1631.8 r0 top
RW10 "22" R_0603#9 1210.6,1633.2 r0 top
RW11 "22" R_0603#9 1210.643,1635.469 r0 top
RW12 "22" R_0603#9 1210.6,1640.6 r0 top
RW13 "22" R_0603#9 1210.563,1642.122 r0 top
RW14 "22" R_0603#9 1210.6,1644.4 r0 top
RW15 "22" R_0603#9 1210.6,1638.4 r0 top
RW16 "22" R_0603#9 1210.6,1629.6 r0 top
RW17 "22" R_0603#6 1208.6,1646.1 r180 top
RW18 "22" R_0603#6 1212.3,1645.8 r180 top
RW19 "4.7K(NC)" R_0603#6 1201.5,1622.3 r0 top
RW20 "4.7K(NC)" R_0603#6 1206.7,1622.3 r180 top
RW21 "0" R_0603#6 1206.7,1625.8 r270 top
S1 "SW SPDT" SW 1214,1662.8 r90 top
SENSOR "DS18B20" TO-92 1067.3,1596.4 r180 top
SPI "10P" IDC10P_2.00 1161.8,1573.2 r180 top
SPKL "CON-2" DIP2_2.0 1125.3,1673.5 r270 top
SPKR "CON-2" DIP2_2.0 1125.3,1667 r270 top
SW2 "NHDS_4" NHDS_4_2.54 1168.9,1578.8 r0 top
TF "10P" IDC10P_2.00 1210,1579 r180 top
TVOUT "AV-8.4-5A" TV 1051.5,1666.6 r0 top
U5 "AT24C02A" SOP-8 1073.2,1628.6 r0 top
U40 "SP3232EEN" SSOP16#1 1168.024,1672.577 r270 top
U41 "SP3232EEN" SSOP16#2 1183.6,1672.5 r270 top
U42 "MAX3485" SOP8 1199.2,1650.3 r90 top
UART1 "CON4" DIP4_2.0 1149.6,1679.9 r0 top
UART2 "CON6" DIP6_2.0 1161.5,1679.9 r0 top
UART3 "CON4" DIP4_2.0 1177.6,1679.9 r0 top
UART4 "CON6" DIP6_1.25 1194.9,1680.3 r180 top
USB1_2 "USB A/F" USBA_2 1054,1689.5 r180 top
USB3_4 "USB A/F" USBA_2 1074.766,1689.576 r180 top
USBOTG "MINIUSB" MINIUSB 1132.5,1691.75 r90 top
UT2 "DM9000AE" DM9000AE 1134.703,1671.004 r270 top
UT3 "AP1117-3.3" TO-252 1180.7,1645.9 r0 top
UT5 "WM8960GEFL" WM8960 1110.928,1671.024 r0 top
UT6 "NJM2561F1" NJM2561F1 1070,1659.9 r270 top
UU1 "FE1.1S" SSOP-28 1067.95,1676 r270 top
WIFI2 "CON16" IDC16_DIP_B 1218.5,1628.1 r0 top locked
X2 "12M" OSC2PR-1 1072.7,1670.2 r90 top
X6 "25M" OSC2PR-1 1141.9,1677.1 r180 top
? "" WEN 1170,1612 r0 top

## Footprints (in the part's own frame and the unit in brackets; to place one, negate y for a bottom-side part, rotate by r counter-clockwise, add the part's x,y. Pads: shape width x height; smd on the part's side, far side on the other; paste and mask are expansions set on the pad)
8P4R_0603 [mm]
  rect 1.2x0.5 smd: 1(0,0) 2(0,-0.889) 3(0,-1.778) 4(0,-2.667) 5(1.874,-2.667) 6(1.874,-1.778) 7(1.874,-0.889) 8(1.874,0)
  silkscreen extent -0.75,-3.15 2.65,0.5
47U1 [mil]
  oct 62x62 hole 35.43: 1(0.24,0.56)
  round 62 hole 35.43: 2(104.49,0.56)
  silkscreen extent -104,-117 168,119
0805C#1 [mm]
  rect 1.3x1.2 smd: 1(0.019,-0.027) 2(0.019,-2.313)
  silkscreen extent -0.99,-3.31 1.01,0.99
0805C#2 [mm]
  rect 1.3x1.2 smd: 1(0.018,-0.022) 2(0.018,-2.308)
  silkscreen extent -0.99,-3.3 1.01,1
0805C#3 [mm]
  rect 1.3x1.2 smd: 1(0.018,0.022) 2(0.018,2.308)
  silkscreen extent -0.99,-1 1.01,3.3
0805C#4 [mm]
  rect 1.3x1.2 smd: 1(0.021,0.018) 2(0.021,2.304)
  silkscreen extent -0.98,-1 1.02,3.3
1000UF [mm]
  oct 2x2 hole 1: 1(4.473,-0.015)
  round 2 hole 1: 2(-0.027,-0.015)
  silkscreen extent -3.2,-5.02 7.89,4.98
1206#1 [mil]
  rect 60x60 smd: 1(-0.21,0.39) 2(134.79,0.39)
  silkscreen extent -50,-50 185,50
1206#2 [mil]
  rect 60x60 smd: 1(0,0) 2(135,0)
  silkscreen extent -50,-50 185,50
3216A#1 [mil]
  rect 60x50 smd: 1(0.46,-0.58) 2(110.46,-0.58)
  silkscreen extent -51,-48 152,46
3216A#2 [mil]
  rect 60x50 smd: 1(0.35,-0.6) 2(110.35,-0.6)
  silkscreen extent -51,-48 151,46
3216A#3 [mil]
  rect 60x50 smd: 1(0,0) 2(110,0)
  silkscreen extent -51,-48 151,46
3216A#4 [mil]
  rect 60x50 smd: 1(0,0) 2(110,0)
  KeepOutLayer region: -90.23,8.85 -90.23,-7.61 3.77,-7.61 3.77,8.85
  silkscreen extent -40,-43 151,44
3216A#5 [mil]
  rect 60x50 smd: 1(0.2,-0.39) 2(110.2,-0.39)
  silkscreen extent -51,-48 151,46
3216a [mil]
  rect 60x50 smd: 1(0.35,-0.6) 2(110.35,-0.6)
  silkscreen extent -51,-48 151,46
BAT600 [mm]
  round 1.1 hole 1.1: 0(0,11.878)
  round 2.54 hole 2.54: 0(0,8.128)
  round 1.5 hole 1.5: 0(0.025,4.378)
  oct 3.5x5 smd: 1(0,0)
  oval 3.5x5 smd: 2(0,16.256)
  silkscreen extent -7.62,0.63 7.62,15.49
BUZZER [mil]
  rect 60x80 hole 40: 1(0,0)
  oval 60x80 hole 40: 2(300,0)
  silkscreen extent -85,-240 395,240
C_0603#1 [mm]
  rect 1.1x1 smd: 1(0,0) 2(1.75,0)
  silkscreen extent -0.7,-0.6 2.5,0.6
C_0603#2 [mm]
  rect 1.1x1 smd: 1(-0.011,-0.005) 2(1.739,-0.005)
  silkscreen extent -0.71,-0.61 2.49,0.59
C_0603#3 [mm]
  rect 1.1x1 smd: 1(0.01,-0.01) 2(1.76,-0.01)
  silkscreen extent -0.69,-0.61 2.51,0.59
C_0603#4 [mm]
  rect 1.1x1 smd: 1(-0.02,-0.014) 2(1.73,-0.014)
  silkscreen extent -0.72,-0.61 2.48,0.59
C_0603#5 [mm]
  rect 1.1x1 smd: 1(0.01,-0.013) 2(1.76,-0.013)
  silkscreen extent -0.69,-0.61 2.51,0.59
C_0603#6 [mm]
  rect 1.1x1 smd: 1(0.003,0.007) 2(1.753,0.007)
  silkscreen extent -0.7,-0.59 2.5,0.61
C_0603#7 [mm]
  rect 1.1x1 smd: 1(0.011,-0.002) 2(1.761,-0.002)
  silkscreen extent -0.69,-0.6 2.51,0.6
C_0603#8 [mm]
  rect 1.1x1 smd: 1(-0.019,0.002) 2(1.731,0.002)
  silkscreen extent -0.72,-0.6 2.48,0.6
C_0603#9 [mm]
  rect 1.1x1 smd: 1(-0.01,0.006) 2(1.74,0.006)
  silkscreen extent -0.71,-0.59 2.49,0.61
C_0603#10 [mm]
  rect 1.1x1 smd: 1(-0.015,-0.005) 2(1.735,-0.005)
  silkscreen extent -0.72,-0.6 2.48,0.6
C_0603#11 [mm]
  rect 1.1x1 smd: 1(-0.015,0.005) 2(1.735,0.005)
  silkscreen extent -0.72,-0.6 2.48,0.6
C_1210#1 [mil]
  rect 70x100 smd: 1(0,0) 2(137.8,0)
  silkscreen extent -61,-75 187,75
C_1210#2 [mil]
  rect 70x100 smd: 1(-0.24,-0.33) 2(137.56,-0.33)
  silkscreen extent -61,-75 187,74
CN2-3.5-180 [mm]
  rect 2x2.5 hole 1: 1(0,0)
  oval 2x2.5 hole 1: 2(-3.5,0)
  silkscreen extent -5.3,-3.57 1.81,3.55
CON6_2.0 [mm]
  rect 1.27x1.27 hole 0.711: 1(0,0)
  round 1.27 hole 0.711: 2(0,2) 3(2,0) 4(2,2) 5(4,0) 6(4,2)
  silkscreen extent -2,-1.5 6,3.5
CON280_SMD_BOT [mm]
  round 3.2 hole 2.2: 0(-0.203,36.939) 0(58.522,37.015)
  rect 2.5x0.4 smd: 1(0,0) 2(5.2,0) 3(0,0.8) 4(5.2,0.8) 5(0,1.6) 6(5.2,1.6) 7(0,2.4) 8(5.2,2.4) 9(0,3.2) 10(5.2,3.2) 11(0,4) 12(5.2,4) 13(0,4.8) 14(5.2,4.8) 15(0,5.6) 16(5.2,5.6) 17(0,6.4) 18(5.2,6.4) 19(0,7.2) 20(5.2,7.2) 21(0,8) 22(5.2,8) 23(0,8.8) 24(5.2,8.8) 25(0,9.6) 26(5.2,9.6) 27(0,10.4) 28(5.2,10.4) 29(0,11.2) 30(5.2,11.2) 31(0,12) 32(5.2,12) 33(0,12.8) 34(5.2,12.8) 35(0,13.6) 36(5.2,13.6) 37(0,14.4) 38(5.2,14.4) 39(0,15.2) 40(5.2,15.2) 41(0,16) 42(5.2,16) 43(0,16.8) 44(5.2,16.8) 45(0,17.6) 46(5.2,17.6) 47(0,18.4) 48(5.2,18.4) 49(0,19.2) 50(5.2,19.2) 51(0,20) 52(5.2,20) 53(0,20.8) 54(5.2,20.8) 55(0,21.6) 56(5.2,21.6) 57(0,22.4) 58(5.2,22.4) 59(0,23.2) 60(5.2,23.2) 61(0,24) 62(5.2,24) 63(0,24.8) 64(5.2,24.8) 65(0,25.6) 66(5.2,25.6) 67(0,26.4) 68(5.2,26.4) 69(0,27.2) 70(5.2,27.2) 71(0,28) 72(5.2,28) 73(0,28.8) 74(5.2,28.8) 75(0,29.6) 76(5.2,29.6) 77(0,30.4) 78(5.2,30.4) 79(0,31.2) 80(5.2,31.2) 201(58.5,31.2) 202(53.3,31.2) 203(58.5,30.4) 204(53.3,30.4) 205(58.5,29.6) 206(53.3,29.6) 207(58.5,28.8) 208(53.3,28.8) 209(58.5,28) 210(53.3,28) 211(58.5,27.2) 212(53.3,27.2) 213(58.5,26.4) 214(53.3,26.4) 215(58.5,25.6) 216(53.3,25.6) 217(58.515,24.795) 218(53.315,24.795) 219(58.515,23.995) 220(53.315,23.995) 221(58.515,23.195) 222(53.315,23.195) 223(58.515,22.395) 224(53.315,22.395) 225(58.515,21.595) 226(53.315,21.595) 227(58.515,20.795) 228(53.315,20.795) 229(58.515,19.995) 230(53.315,19.995) 231(58.515,19.195) 232(53.315,19.195) 233(58.515,18.395) 234(53.315,18.395) 235(58.515,17.595) 236(53.315,17.595) 237(58.515,16.795) 238(53.315,16.795) 239(58.515,15.995) 240(53.315,15.995) 241(58.515,15.195) 242(53.315,15.195) 243(58.515,14.395) 244(53.315,14.395) 245(58.515,13.595) 246(53.315,13.595) 247(58.515,12.795) 248(53.315,12.795) 249(58.515,11.995) 250(53.315,11.995) 251(58.515,11.195) 252(53.315,11.195) 253(58.515,10.395) 254(53.315,10.395) 255(58.515,9.595) 256(53.315,9.595) 257(58.515,8.795) 258(53.315,8.795) 259(58.515,7.995) 260(53.315,7.995) 261(58.515,7.195) 262(53.315,7.195) 263(58.515,6.395) 264(53.315,6.395) 265(58.515,5.595) 266(53.315,5.595) 267(58.515,4.795) 268(53.315,4.795) 269(58.515,3.995) 270(53.315,3.995) 271(58.515,3.195) 272(53.315,3.195) 273(58.515,2.395) 274(53.315,2.395) 275(58.515,1.595) 276(53.315,1.595) 277(58.515,0.795) 278(53.315,0.795) 279(58.515,-0.005) 280(53.315,0.006)
  rect 0.4x2.5 smd: 81(2.165,46.497) 82(2.165,41.297) 83(2.965,46.497) 84(2.965,41.297) 85(3.765,46.497) 86(3.765,41.297) 87(4.565,46.497) 88(4.565,41.297) 89(5.365,46.497) 90(5.365,41.297) 91(6.165,46.497) 92(6.165,41.297) 93(6.965,46.497) 94(6.965,41.297) 95(7.765,46.497) 96(7.765,41.297) 97(8.565,46.497) 98(8.565,41.297) 99(9.365,46.497) 100(9.365,41.297) 101(10.165,46.497) 102(10.165,41.297) 103(10.965,46.497) 104(10.965,41.297) 105(11.765,46.497) 106(11.765,41.297) 107(12.565,46.497) 108(12.565,41.297) 109(13.365,46.497) 110(13.365,41.297) 111(14.165,46.497) 112(14.165,41.297) 113(14.965,46.497) 114(14.965,41.297) 115(15.765,46.497) 116(15.765,41.297) 117(16.565,46.497) 118(16.565,41.297) 119(17.365,46.497) 120(17.365,41.297) 121(18.171,46.506) 122(18.171,41.306) 123(18.971,46.506) 124(18.971,41.306) 125(19.771,46.506) 126(19.771,41.306) 127(20.571,46.506) 128(20.571,41.306) 129(21.371,46.506) 130(21.371,41.306) 131(22.171,46.506) 132(22.171,41.306) 133(22.971,46.506) 134(22.971,41.306) 135(23.771,46.506) 136(23.771,41.306) 137(24.571,46.506) 138(24.571,41.306) 139(25.371,46.506) 140(25.371,41.306) 141(33.096,46.506) 142(33.096,41.306) 143(33.896,46.506) 144(33.896,41.306) 145(34.696,46.506) 146(34.696,41.306) 147(35.496,46.506) 148(35.496,41.306) 149(36.296,46.506) 150(36.296,41.306) 151(37.096,46.506) 152(37.096,41.306) 153(37.896,46.506) 154(37.896,41.306) 155(38.696,46.506) 156(38.696,41.306) 157(39.496,46.506) 158(39.496,41.306) 159(40.296,46.506) 160(40.296,41.306) 161(41.096,46.506) 162(41.096,41.306) 163(41.896,46.506) 164(41.896,41.306) 165(42.696,46.506) 166(42.696,41.306) 167(43.496,46.506) 168(43.496,41.306) 169(44.296,46.506) 170(44.296,41.306) 171(45.096,46.506) 172(45.096,41.306) 173(45.896,46.506) 174(45.896,41.306) 175(46.696,46.506) 176(46.696,41.306) 177(47.496,46.506) 178(47.496,41.306) 179(48.296,46.506) 180(48.296,41.306) 181(49.096,46.506) 182(49.096,41.306) 183(49.896,46.506) 184(49.896,41.306) 185(50.696,46.506) 186(50.696,41.306) 187(51.496,46.506) 188(51.496,41.306) 189(52.296,46.506) 190(52.296,41.306) 191(53.096,46.506) 192(53.096,41.306) 193(53.896,46.506) 194(53.896,41.306) 195(54.696,46.506) 196(54.696,41.306) 197(55.496,46.506) 198(55.496,41.306) 199(56.296,46.506) 200(56.296,41.306)
  KeepOutLayer circle w0.254: c55.915,33.709 r0.35
  KeepOutLayer circle w0.254: c2.597,-2.507 r0.35
  KeepOutLayer circle w0.254: c2.622,33.739 r0.5
  KeepOutLayer circle w0.254: c55.915,-2.491 r0.5
  KeepOutLayer circle w0.254: c27.872,43.899 r0.5
  KeepOutLayer circle w0.254: c-0.353,43.924 r0.35
  KeepOutLayer circle w0.254: c58.822,43.924 r0.5
  KeepOutLayer circle w0.254: c30.572,43.924 r0.35
  silkscreen extent -2.25,-4.14 60.8,48.92
D1206 [mm]
  rect 1.5x2 smd: 1(0,0) 2(3.5,0)
  silkscreen extent 1.25,-1 2.25,1
DB9RA/M [mil]
  rect 62x62 hole 38: 1(0,0)
  round 62 hole 38: 2(109,0) 3(218,0) 4(327,0) 5(436,0) 6(55,-100) 7(164,-100) 8(273,-100) 9(382,-100)
  round 150 hole 118.11: ""(-275,-50) ""(711,-50)
  silkscreen extent -404,-679 837,79
DC-JACK [mil]
  oval 120x150 hole 102: 1(0,0) 2(229,0)
  oval 150x120 hole 102: 3(103,186)
  silkscreen extent 11,-173 530,173
DIP2_2.0 [mm]
  rect 1.2x2.4 hole 0.9: 1(0.002,0.002)
  oval 1.2x2.4 hole 0.9: 2(2.002,0.002)
  silkscreen extent -2,-2 4,3
DIP4_2.0 [mm]
  rect 1.2x2.4 hole 0.9: 1(0,0)
  oval 1.2x2.4 hole 0.9: 2(2,0) 3(4,0) 4(6,0)
  silkscreen extent -2,-2 8,3
DIP6_1.25 [mil]
  rect 32x50 hole 24: 1(0,0)
  oval 32x50 hole 24: 2(49.21,0) 3(98.42,0) 4(147.64,0) 5(196.85,0) 6(246.06,0)
  silkscreen extent -51,-55 295,56
DIP6_2.0 [mm]
  rect 1.2x2.4 hole 0.9: 1(0.008,0.002)
  oval 1.2x2.4 hole 0.9: 2(2.008,0.002) 3(4.008,0.002) 4(6.008,0.002) 5(8.008,0.002) 6(10.008,0.002)
  silkscreen extent -1.99,-2 12.01,3
DIP8_2.0 [mm]
  rect 1.2x2.4 hole 0.8: 1(-0.012,-0.002)
  oval 1.2x2.4 hole 0.8: 2(1.988,-0.002) 3(3.988,-0.002) 4(5.988,-0.002) 5(7.988,-0.002) 6(9.988,-0.002) 7(11.988,-0.002) 8(13.988,-0.002)
  silkscreen extent -2.01,-2 15.99,3
DM9000AE [mm]
  rect 0.3x1.5 smd: 1(0,0)
  oval 0.3x1.5 smd: 2(0.5,0) 3(1,0) 4(1.5,0) 5(2,0) 6(2.5,0) 7(3,0) 8(3.5,0) 9(4,0) 10(4.5,0) 11(5,0) 12(5.5,0) 25(5.5,9) 26(5,9) 27(4.5,9) 28(4,9) 29(3.5,9) 30(3,9) 31(2.5,9) 32(2,9) 33(1.5,9) 34(1,9) 35(0.5,9) 36(0,9)
  oval 1.5x0.3 smd: 13(7.25,1.75) 14(7.25,2.25) 15(7.25,2.75) 16(7.25,3.25) 17(7.25,3.75) 18(7.25,4.25) 19(7.25,4.75) 20(7.25,5.25) 21(7.25,5.75) 22(7.25,6.25) 23(7.25,6.75) 24(7.25,7.25) 37(-1.75,7.25) 38(-1.75,6.75) 39(-1.75,6.25) 40(-1.75,5.75) 41(-1.75,5.25) 42(-1.75,4.75) 43(-1.75,4.25) 44(-1.75,3.75) 45(-1.75,3.25) 46(-1.75,2.75) 47(-1.75,2.25) 48(-1.75,1.75)
  silkscreen extent -1.75,0 7.25,9
DWK [mm]
  round 0.8 hole 0.3: 1(-2.032,0) 1(-1.778,-2.032) 1(-1.651,2.286) 1(0,-3.048) 1(0,3.048) 1(1.651,2.159) 1(1.778,-2.032) 1(2.032,0)
  round 5 hole 3: 1(0,-1) 1(0,0) 1(0,1)
  silkscreen extent -3.08,-4.02 2.92,3.99
FPC0.5-SMT-40P [mm]
  rect 0.25x1.6 smd: 1(0,0) 2(0.5,0) 3(1,0) 4(1.5,0) 5(2,0) 6(2.5,0) 7(3,0) 8(3.5,0) 9(4,0) 10(4.5,0) 11(5,0) 12(5.5,0) 13(6,0) 14(6.5,0) 15(7,0) 16(7.5,0) 17(8,0) 18(8.5,0) 19(9,0) 20(9.5,0) 21(10,0) 22(10.5,0) 23(11,0) 24(11.5,0) 25(12,0) 26(12.5,0) 27(13,0) 28(13.5,0) 29(14,0) 30(14.5,0) 31(15,0) 32(15.5,0) 33(16,0) 34(16.5,0) 35(17,0) 36(17.5,0) 37(18,0) 38(18.5,0) 39(19,0) 40(19.5,0)
  rect 2x2 smd: A(-2.249,3.489) B(21.751,3.489)
  silkscreen extent -4.9,-2.54 24,5.03
FUSE [mil]
  rect 100x140 smd: 1(0,0) 2(180,0)
  silkscreen extent 0,-80 180,80
HDMI [mm]
  rect 2.5x0.25 smd: 1(0,0)
  oval 2.5x0.25 smd: 2(0,0.5) 3(0,1) 4(0,1.5) 5(0,2) 6(0,2.5) 7(0,3) 8(0,3.5) 9(0,4) 10(0,4.5) 11(0,5) 12(0,5.5) 13(0,6) 14(0,6.5) 15(0,7) 16(0,7.5) 17(0,8) 18(0,8.5) 19(0,9)
  oval 2.5x2 hole 1.3: 20(-7.491,11.75) 21(-7.491,-2.75)
  oval 3.5x2.8 hole 2.3: 22(-1.5,11.75) 23(-1.5,-2.75)
  silkscreen extent -12,-2.75 2.01,11.75
HR911105A [mm]
  rect 1.575x1.575 hole 0.889: 1(0,0)
  round 1.575 hole 0.889: 2(-2.54,1.27) 3(0,2.54) 4(-2.54,3.81) 5(0,5.08) 6(-2.54,6.35) 7(0,7.62) 8(-2.54,8.89)
  round 1.8 hole 1.02: 9(11.25,-2.18) 10(11.25,0.36) 11(11.25,8.53) 12(11.25,11.07)
  round 2.5 hole 1.63: A(3.3,-3.3) B(3.3,12.19)
  round 3.25 hole 3.25: C(6.35,10.16) D(6.35,-1.27)
  silkscreen extent -4.23,-3.55 17.35,12.45
IDC10P_2.00 [mm]
  rect 1.27x1.27 hole 0.7: 1(0,0)
  round 1.27 hole 0.7: 2(-0.011,2.011) 3(1.989,0.011) 4(1.989,2.011) 5(3.989,0.011) 6(3.989,2.011) 7(5.989,0.011) 8(5.989,2.011) 9(7.989,0.011) 10(7.989,2.011)
  silkscreen extent -1.97,-2.02 9.65,3.56
IDC10S [mm]
  rect 1.2x1.2 hole 0.7: 1(0.004,-0.012)
  round 1.2 hole 0.7: 2(0.004,1.988) 3(2.004,-0.012) 4(2.004,1.988) 5(4.004,-0.012) 6(4.004,1.988) 7(6.004,-0.012) 8(6.004,1.988) 9(8.004,-0.012) 10(8.004,1.988)
  silkscreen extent -4.75,-2.03 12.75,3.49
IDC14S_2.0 [mm]
  rect 1.2x1.2 hole 0.7: 1(0,0)
  round 1.2 hole 0.7: 2(0,2) 3(2,0) 4(2,2) 5(4,0) 6(4,2) 7(6,0) 8(6,2) 9(8,0) 10(8,2) 11(10,0) 12(10,2) 13(12,0) 14(12,2)
  silkscreen extent -4.75,-2.25 16.75,3.5
IDC16_DIP_B [mm]
  rect 1.2x1.2 hole 0.7: 1(0.012,-0.012)
  round 1.2 hole 0.7: 2(-1.988,-0.012) 3(0.012,1.988) 4(-1.988,1.988) 5(0.012,3.988) 6(-1.988,3.988) 7(0.012,5.988) 8(-1.988,5.988) 9(0.012,7.988) 10(-1.988,7.988) 11(0.012,9.988) 12(-1.988,9.988) 13(0.012,11.988) 14(-1.988,11.988) 15(0.012,13.988) 16(-1.988,13.988)
  silkscreen extent -26.49,-5.01 2.51,18.99
IDC20S_2.0 [mm]
  rect 1.2x1.2 hole 0.7: 1(0,0)
  round 1.2 hole 0.7: 2(0,2) 3(2,0) 4(2,2) 5(4,0) 6(4,2) 7(6,0) 8(6,2) 9(8,0) 10(8,2) 11(10,0) 12(10,2) 13(12,0) 14(12,2) 15(14,0) 16(14,2) 17(16,0) 18(16,2) 19(18,0) 20(18,2)
  silkscreen extent -4.75,-2.25 22.75,3.5
IDC24P_2.0 [mm]
  rect 1.27x1.27 hole 0.7: 1(0,0)
  round 1.27 hole 0.7: 2(0,2) 3(2,0) 4(2,2) 5(4,0) 6(4,2) 7(6,0) 8(6,2) 9(8,0) 10(8,2) 11(10,0) 12(10,2) 13(12,0) 14(12,2) 15(14,0) 16(14,2) 17(16,0) 18(16,2) 19(18,0) 20(18,2) 21(20,0) 22(20,2) 23(22,0) 24(22,2)
  silkscreen extent -1.96,-2.03 23.94,3.5
IDC40P_2.00 [mm]
  rect 1.27x1.27 hole 0.7: 1(0,0)
  round 1.27 hole 0.7: 2(0,2) 3(2,0) 4(2,2) 5(4,0) 6(4,2) 7(6,0) 8(6,2) 9(8,0) 10(8,2) 11(10,0) 12(10,2) 13(12,0) 14(12,2) 15(14,0) 16(14,2) 17(16,0) 18(16,2) 19(18,0) 20(18,2) 21(20,0) 22(20,2) 23(22,0) 24(22,2) 25(24,0) 26(24,2) 27(26,0) 28(26,2) 29(28,0) 30(28,2) 31(30,0) 32(30,2) 33(32,0) 34(32,2) 35(34,0) 36(34,2) 37(36,0) 38(36,2) 39(38,0) 40(38,2)
  silkscreen extent -1.96,-2.03 39.94,3.5
IRM3638 [mil]
  oval 40x60 hole 30: 1(0,0) 2(100,0) 3(200,0)
  silkscreen extent -30,-143 230,50
LAJITONG [mm]
  silkscreen extent -4.19,-5.11 4.14,6.12
LED_0805#1 [mm]
  rect 1.4x1.27 smd: 1(2.21,0) 2(0,0)
  silkscreen extent -0.8,-0.89 3.01,0.89
LED_0805#2 [mm]
  rect 1.4x1.27 smd: 1(2.202,0) 2(-0.008,0)
  silkscreen extent -0.81,-0.89 3,0.89
MIC [mm]
  rect 1.2x2.4 hole 0.9: 1(0,0)
  oval 1.2x2.4 hole 0.9: 2(2.54,0)
  silkscreen extent -1.73,-3 4.27,3
MINIUSB [mm]
  rect 2.5x0.4 smd: 1(0,0)
  oval 2.5x0.4 smd: 2(0,0.8) 3(0,1.6) 4(0,2.4) 5(0,3.2)
  rect 2.54x1.524 smd: 6(1.25,5.85) 6(1.279,-2.819)
  rect 2.667x1.524 smd: 6(6.5,-2.8) 6(6.5,5.85)
  KeepOutLayer circle w0.254: c3.54,-0.55 r0.7
  KeepOutLayer circle w0.254: c3.54,3.75 r0.7
  silkscreen extent -0.52,-2.55 8.57,5.63
NHDS_4_2.54 [mm]
  rect 3x1.2 smd: 1(0,0) 2(0,-2.54) 3(0,-5.08) 4(0,-7.62) 5(9.144,-7.62) 6(9.144,-5.08) 7(9.144,-2.54) 8(9.144,0)
  silkscreen extent 2.03,-8.89 7.08,1.27
NJM2561F1 [mm]
  rect 1.2x0.5 smd: 1(-0.012,-0.005)
  oval 1.2x0.5 smd: 2(-0.012,-0.955) 3(-0.012,-1.905) 4(2.488,-1.905) 5(2.488,-0.955) 6(2.488,-0.005)
  silkscreen extent 0.76,-2.38 1.71,0.47
OSC2PR-1 [mil]
  round 60 hole 32: 1(0,0) 2(197,0)
  silkscreen extent -123,-92 327,88
PJ-215-B [mm]
  oval 2.2x2.5 hole 1.6: 1(0,0) 2(2.2,2) 3(7.7,2) 10(11.7,0) 11(5.9,0)
  silkscreen extent -5.3,-4 12.9,4.2
R_0603#1 [mm]
  rect 1.1x1 smd: 1(-0.02,-0.002) 2(1.73,-0.002)
  silkscreen extent -0.02,-0.6 1.68,0.6
R_0603#2 [mm]
  rect 1.1x1 smd: 1(0,0) 2(1.75,0)
  silkscreen extent 0,-0.6 1.7,0.6
R_0603#3 [mm]
  rect 1.1x1 smd: 1(-0.008,0.011) 2(1.742,0.011)
  silkscreen extent -0.01,-0.59 1.69,0.61
R_0603#4 [mm]
  rect 1.1x1 smd: 1(0.011,0.002) 2(1.761,0.002)
  silkscreen extent 0.01,-0.6 1.71,0.6
R_0603#5 [mm]
  rect 1.1x1 smd: 1(-0.002,0.005) 2(1.748,0.005)
  silkscreen extent 0,-0.59 1.7,0.61
R_0603#6 [mm]
  rect 1.1x1 smd: 1(0.021,-0.005) 2(1.771,-0.005)
  silkscreen extent 0.02,-0.61 1.72,0.59
R_0603#7 [mm]
  rect 1.1x1 smd: 1(-0.022,-0.022) 2(1.728,-0.022)
  silkscreen extent -0.02,-0.62 1.68,0.58
R_0603#8 [mm]
  rect 1.1x1 smd: 1(-0.01,-0.011) 2(1.74,-0.011)
  silkscreen extent -0.01,-0.61 1.69,0.59
R_0603#9 [mm]
  rect 1.1x1 smd: 1(0.021,0.005) 2(1.771,0.005)
  silkscreen extent 0.02,-0.6 1.72,0.6
RESD1 [mil]
  round 60 hole 30: 1(0.21,-0.31) 2(200.21,-0.31)
  rect 60x55.68 smd: 1(40.21,-0.31) 2(160.21,-0.31)
  rect 31.5x31.5 smd rot 45: 1(70.21,-0.31) 2(130.21,-0.31)
  silkscreen extent -59,-60 259,59
RP2 [mm]
  oval 2x1.6 hole 1.2: 1(0,0) 2(5.5,-2.5) 3(0,-5.048)
  silkscreen extent -1.5,-6 5.5,1
RST_KEY [mm]
  round 1.6 hole 0.9: 1(0,0) 2(4.8,0)
  oval 2.2x1.6 hole 1.4: A(6.05,-2.75) B(-1.25,-2.75)
  silkscreen extent -1.25,-3.75 6.05,3.65
S9013SMD#1 [mil]
  rect 40x50 smd: B(-38,-85) C(0,0) E(37,-85)
  silkscreen extent -58,-45 57,-5
S9013SMD#2 [mil]
  rect 40x50 smd: B(-37.5,-84.99) C(0.5,0.01) E(37.5,-84.99)
  silkscreen extent -58,-45 57,-5
SD-5011 [mm]
  rect 2.8x1 smd: 1(0,0) 2(0,-2.5) 3(0,-5.8) 4(0,-7.4) 5(0,-9.9) 6(0,-12.4) 7(0,-14.8) 8(0,-16.5) 9(0,2.5) 11(0,-4.1)
  rect 2.8x1.2 smd: 10(0,-19.9)
  rect 3x3.5 smd: 13(22.8,-22) 14(21.8,8)
  round 2 hole 2: ""(24.946,5.1) ""(25.2,5.1)
  round 1.5 hole 1.5: ""(25.046,-19.1)
  silkscreen extent 1.8,-21.25 30.05,7.5
SIP2_2.0 [mm]
  rect 1.4x1.4 hole 0.8: 1(0,0)
  round 1.4 hole 0.8: 2(2,0)
  silkscreen extent -0.98,-1 3.02,1
SMBJ_SMD [mm]
  rect 3x3 smd: 1(0,0) 2(-4.5,0)
  silkscreen extent -4.55,-2 0,2
SOP8 [mm]
  rect 2x0.55 smd: 1(0.011,-0.009)
  oval 2x0.55 smd: 2(0.011,-1.279) 3(0.011,-2.549) 4(0.011,-3.819) 5(6.011,-3.819) 6(6.011,-2.549) 7(6.011,-1.279) 8(6.011,-0.009)
  silkscreen extent 1.8,-4.45 4.23,0.63
SOP-8 [mm]
  rect 1.5x0.635 smd: 1(-0.006,0.012) 2(-0.006,-1.258) 3(-0.006,-2.528) 4(-0.006,-3.798) 5(5.994,-3.798) 6(5.994,-2.528) 7(5.994,-1.258) 8(5.994,0.012)
  silkscreen extent 0.99,-4.49 4.99,0.7
SOT23-3 [mm]
  rect 0.8x1.2 smd: 1(0.006,-0.03) 2(2.006,-0.03) 3(1.006,2.745)
  silkscreen extent -0.52,0.65 2.56,2.05
SSOP16#1 [mil]
  oval 80x24 smd: 1(-0.03,0.18) 2(-0.03,-49.82) 3(-0.03,-99.82) 4(-0.03,-149.82) 5(-0.03,-199.82) 6(-0.03,-249.82) 7(-0.03,-299.82) 8(-0.03,-349.82) 9(219.97,-349.82) 10(219.97,-299.82) 11(219.97,-249.82) 12(219.97,-199.82) 13(219.97,-149.82) 14(219.97,-99.82) 15(219.97,-49.82) 16(219.97,0.18)
  silkscreen extent 60,-350 160,25
SSOP16#2 [mil]
  oval 80x24 smd: 1(0,0) 2(0,-50) 3(0,-100) 4(0,-150) 5(0,-200) 6(0,-250) 7(0,-300) 8(0,-350) 9(220,-350) 10(220,-300) 11(220,-250) 12(220,-200) 13(220,-150) 14(220,-100) 15(220,-50) 16(220,0)
  silkscreen extent 60,-350 160,25
SSOP-28 [mm]
  oval 1.6x0.3 smd: 1(0,0) 2(0,-0.635) 3(0,-1.27) 4(0,-1.905) 5(0,-2.54) 6(0,-3.175) 7(0,-3.81) 8(0,-4.445) 9(0,-5.08) 10(0,-5.715) 11(0,-6.35) 12(0,-6.985) 13(0,-7.62) 14(0,-8.255) 15(6.096,-8.255) 16(6.096,-7.62) 17(6.096,-6.985) 18(6.096,-6.35) 19(6.096,-5.715) 20(6.096,-5.08) 21(6.096,-4.445) 22(6.096,-3.81) 23(6.096,-3.175) 24(6.096,-2.54) 25(6.096,-1.905) 26(6.096,-1.27) 27(6.096,-0.635) 28(6.096,0)
  silkscreen extent 1.14,-9.06 4.9,0.7
SW [mm]
  oval 2x3 hole 1.2: 1(2.996,-0.008) 2(-0.004,-0.008) 3(5.996,-0.008)
  oval 3x4 hole 1.5: 4(-3.504,-1.008) 5(9.496,-1.008)
  silkscreen extent -3.5,-11.97 9.5,1.49
SW-PB2 [mm]
  rect 1.2x2.5 smd: 1(0,0) 2(0,-7)
  silkscreen extent -2,-6.75 2,-0.25
TO-92 [mm]
  rect 0.8x1.5 hole 0.6: 1(3.048,0)
  oval 0.8x1.5 hole 0.6: 2(1.269,0.001) 3(-0.508,0)
  silkscreen extent -1.72,-2.45 4.28,2.03
TO-252 [mm]
  rect 1.4x2 smd: 1(0,0) 2(2.311,0) 3(4.623,0)
  rect 7x9 smd: 4(2.3,7.3)
  silkscreen extent -1.72,1.52 6.26,7.51
TV [mm]
  round 4 hole 2.4: 1(0,0) 2(-4.896,0)
  KeepOutLayer lines w0.254: -9,-5.25 -6.75,-5.25 -6.75,-3 -9,-3 -9,-5.25 ; -8.7,3 -6.5,3 -6.5,5.25 -8.7,5.25 -8.7,3
  silkscreen extent -17.8,-5 0.7,5
USBA_2 [mm]
  oct 1.6x1.6 hole 0.92: 1(0,0)
  round 1.6 hole 0.92: 2(2.5,0) 3(4.5,0) 4(7,0) 5(0,2.62) 6(2.5,2.62) 7(4.5,2.62) 8(7,2.62)
  round 3.3 hole 2.2: 9(-4,2.99) 9(-3.5,2.99) 10(10.5,2.99) 10(11,2.99) 11(-4,-2.69) 11(-3.5,-2.69) 12(10.5,-2.69) 12(11,-2.69)
  silkscreen extent -4,-13.38 11,4.87
WEN [mm]
  silkscreen extent -7.45,-5.83 7.08,6.16
WM8960 [mm]
  oval 1x0.25 smd: 1(0,0) 2(0,-0.5) 3(0,-1) 4(0,-1.5) 5(0,-2) 6(0,-2.5) 7(0,-3) 8(0,-3.5) 17(4.95,-3.5) 18(4.95,-3) 19(4.95,-2.5) 20(4.95,-2) 21(4.95,-1.5) 22(4.95,-1) 23(4.95,-0.5) 24(4.95,0)
  oval 0.25x1 smd: 9(0.725,-4.225) 10(1.225,-4.225) 11(1.725,-4.225) 12(2.225,-4.225) 13(2.725,-4.225) 14(3.225,-4.225) 15(3.725,-4.225) 16(4.225,-4.225) 25(4.225,0.725) 26(3.725,0.725) 27(3.225,0.725) 28(2.725,0.725) 29(2.225,0.725) 30(1.725,0.725) 31(1.225,0.725) 32(0.725,0.725)
  rect 3.45x3.45 smd: 33(2.5,-1.75)
  silkscreen extent -0.25,-4.25 5,1

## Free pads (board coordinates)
  round 5 hole 3.2: 2(1073.506,1587.088) 2(1073.506,1663.923) 2(1190.092,1587.088) 2(1190.092,1663.923) 2(1194.5,1625.6)

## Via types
v1: diameter 1, hole 0.5, TopLayer to BottomLayer, 458 vias
v2: diameter 0.8, hole 0.4, TopLayer to BottomLayer, 172 vias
